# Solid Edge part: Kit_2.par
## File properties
Sűrűség: 0,000 kg/m^3
Pontosság: 0,990
Author: ahadarics
Last saved by: psaghy
Revision: 78
Username: ahadarics
Dokumentum tartalom típus: 0
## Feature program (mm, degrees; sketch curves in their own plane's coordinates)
base feature "unnamed BaseFeature 1"
sketch for "Furat_1" plane through (0, 0, -180) normal (0, 0, -1) x-axis (1, 0, 0)
  hole centre (-70, 70) bore radius 6.9175
hole "Furat_1" nominal diameter 16 finite  ThreadDepth = 24 mm
sketch for "unnamed Hole 1" plane through (0, 0, -180) normal (0, 0, -1) x-axis (1, 0, 0)
  hole centre (-70, -70) bore radius 6.9175
hole "unnamed Hole 1" finite
sketch for "unnamed Hole 2" plane through (0, 0, -180) normal (0, 0, -1) x-axis (1, 0, 0)
  hole centre (70, -70) bore radius 6.9175
hole "unnamed Hole 2" finite
sketch for "unnamed Hole 3" plane through (0, 0, -180) normal (0, 0, -1) x-axis (1, 0, 0)
  hole centre (70, 70) bore radius 6.9175
hole "unnamed Hole 3" finite
pattern "unnamed Pattern 1" of "Furat_1", "unnamed Hole 1", "unnamed Hole 2", "unnamed Hole 3"
sketch for "Furat_5" plane through (15, -89, -154.5) normal (0, -1, 0) x-axis (0, 0, -1)
hole "Furat_5" diameter 26.441 finite  ThreadDepth = 26.5 mm
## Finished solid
Body 1: solid body, 567 faces, 1361 edges, 837 vertices, 2 internal voids.
  Faces by surface: cylinder 199, plane 169, torus 112, spline 35, cone 27, swept 19, sphere 6
  Edges by curve: line 486, circle 421, curve on surface 397, spline 39, intersection 17, ellipse 1
Bounding box of the edges (mm; curved faces can reach further): 180.000 x 180.000 x 56.000, from (-90, -90, -186) to (90, 90, -130).
Cylindrical faces by radius (mm): R0.4595 x1, R0.4687 x1, R0.4912 x1, R0.5036 x1, R0.5393 x1, R0.5619 x1, R0.5738 x1, R0.5925 x1, R0.6033 x1, R0.6109 x1, R0.6502 x1, R0.6626 x1, R0.6941 x1, R0.7492 x1, R0.7991 x1, R0.8155 x1, R0.8225 x1, R0.8523 x1, R0.8677 x1, R0.9066 x1, R0.9072 x1, R0.9188 x1, R0.9543 x1, R0.9562 x1, R1 x56, R1.0016 x2, R1.0018 x2, R1.0083 x12, R1.0187 x1, R1.0708 x1, R1.1067 x1, R1.3671 x1, R1.5039 x1, R1.5591 x1, R1.5808 x1, R1.6101 x1, R1.6481 x1, R1.7807 x1, R1.8842 x1, R1.9083 x2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
Conical faces (half-angle, radius in mm at the cone's reference point): 45 deg R3.85 x1, 45 deg R4.25 x1, 45 deg R6.91 x12, 45 deg R8.9 x8, 45 deg R12.055 x1, 45 deg R18.75 x4
Toroidal faces (ring radius, tube radius in mm): R1 r1 x14, R2 r1 x9, R2.0239 r1.0015 x11, R3 r1 x3, R3.005 r1.0019 x12, R3.0108 r1.0019 x6, R4 r1 x8, R5.85 r0.2 x1, R11 r1 x1, R12 r0.5 x12, R13.8 r0.8 x4, R15 r2 x1, R16 r1 x1, R18 r1 x5, R19 r1 x4, R20 r1 x8, R21 r2 x4, R31.5 r1 x1, R35.25 r2 x7
Spherical faces by radius (mm): R1 x6
Planar faces by outward normal: +x 12, +y 5, +z 13, -x 13, -y 27, -z 49, oblique 50
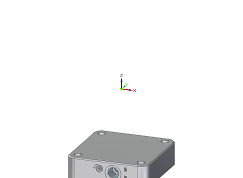
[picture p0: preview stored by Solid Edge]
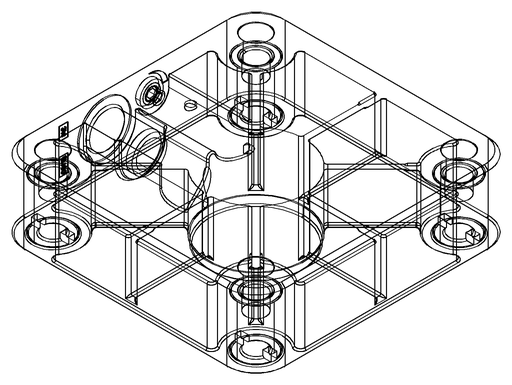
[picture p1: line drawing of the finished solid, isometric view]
